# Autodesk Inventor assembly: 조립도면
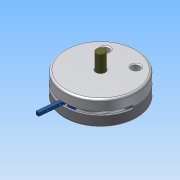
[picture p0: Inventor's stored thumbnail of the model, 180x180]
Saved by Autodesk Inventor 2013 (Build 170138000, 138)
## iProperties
Created: 2015-04
Part Number: 조립도면
Document SubType Name: Assembly
Designer: Administrator
Author: Administrator
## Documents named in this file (10)
- C:\Users\Administrator\Desktop\450406V1034\조립도면.iam
- C:\Users\Administrator\Desktop\450406V1034\본체.ipt
- C:\Users\Administrator\Desktop\450406V1034\M 10 x 35.ipt
- C:\Users\Administrator\Desktop\450406V1034\덮개.ipt
- C:\Users\Administrator\Desktop\450406V1034\멈춤링.ipt
- C:\Users\Administrator\Desktop\450406V1034\베어링62_22.ipt
- C:\Users\Administrator\Desktop\450406V1034\슬라이더.ipt
- C:\Users\Administrator\Desktop\450406V1034\슬라이더2.ipt
- C:\Users\Administrator\Desktop\450406V1034\축.ipt
- C:\Users\Administrator\Desktop\450406V1034\평행핀.ipt
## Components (2 placed, 1 different names)
1. M 10 x 35:1
2. M 10 x 35:2
